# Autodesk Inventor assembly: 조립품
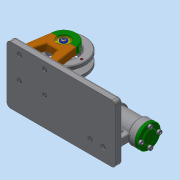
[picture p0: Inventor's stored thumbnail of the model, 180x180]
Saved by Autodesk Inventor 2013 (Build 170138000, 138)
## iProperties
Created: 2018-01
Part Number: 조립품
Document SubType Name: Assembly
Designer: dgall
Mass: 865.892 g
Surface Area: 888.145 cm^2
Volume: 224.242 cm^3
Density: 3.86141 g/cm^3
Author: dgall
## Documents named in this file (19)
- C:\Users\dgall\Desktop\380107V1016\조립품.iam
- C:\Users\dgall\Desktop\380107V1016\플레이트.ipt
- C:\Users\dgall\Desktop\380107V1016\지지대-A.ipt
- C:\Users\dgall\Desktop\380107V1016\베어링커버-A.ipt
- C:\Users\dgall\Desktop\380107V1016\베어링 8x22x7.ipt
- C:\Users\dgall\Desktop\380107V1016\스페이서.ipt
- C:\Users\dgall\Desktop\380107V1016\V-벨트풀리.ipt
- C:\Users\dgall\Desktop\380107V1016\크랭크축.ipt
- C:\Users\dgall\Desktop\380107V1016\하우징.ipt
- C:\Users\dgall\Desktop\380107V1016\하우징커버-A.ipt
- C:\Users\dgall\Desktop\380107V1016\하우징커버-B.ipt
- C:\Users\dgall\Desktop\380107V1016\플랜지.ipt
- C:\Users\dgall\Desktop\380107V1016\커넥팅로드-A.ipt
- C:\Users\dgall\Desktop\380107V1016\커넥팅로드-B.ipt
- C:\Users\dgall\Desktop\380107V1016\피스톤.ipt
- C:\Users\dgall\Desktop\380107V1016\3mm 와셔.ipt
- C:\Users\dgall\Desktop\380107V1016\볼트 M3x8.ipt
- C:\Users\dgall\Desktop\380107V1016\볼트 M3x12.ipt
- C:\Users\dgall\Desktop\380107V1016\둥근머리볼트 M3x12.ipt
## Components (9 placed, 8 different names)
1. 플레이트:1
2. V-벨트풀리:1
3. 하우징:1
4. 하우징커버-A:1
5. 하우징커버-B:1
6. 플랜지:1
7. 피스톤:1
8. 3mm 와셔:1
9. 3mm 와셔:2
